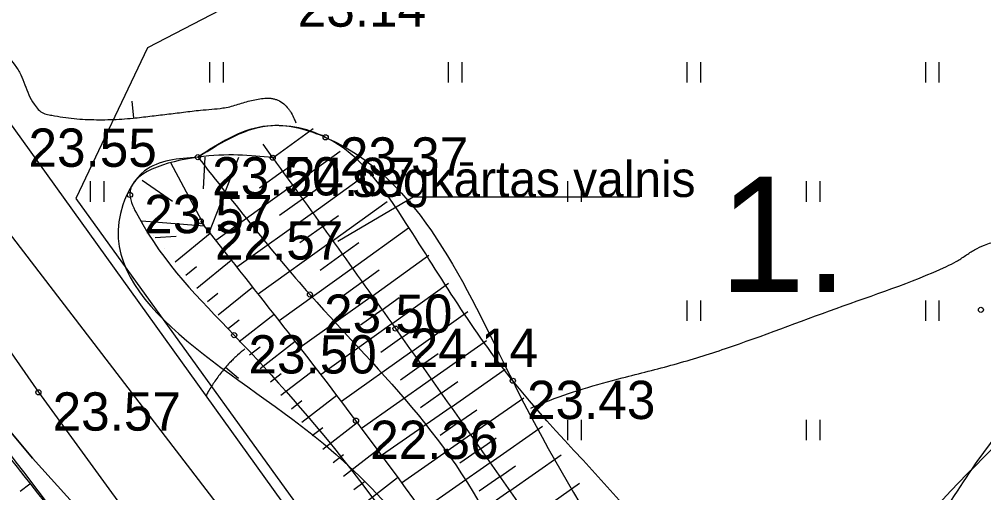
# Model space of a CAD drawing. Extents: x 521824 to 524158, y 294774 to 296228.
# Drawn here: x 522148.91 to 522177.2, y 295839.46 to 295853.36 of the extents above; entities that cross this region are included whole.
import ezdxf

# ---------------------------------------------------------------- set-up
doc = ezdxf.new("R2010")
doc.units = 0
for name, color, linetype in [('7315030100', 7, 'Continuous'), ('CELI_CMAL_####_####_#', 7, 'Continuous'), ('GL4 Segkartas izplatības laukums', 7, 'Continuous'), ('GL7 Citi Izplatības laukumi', 7, 'Continuous'), ('RELJ_AATZ_####_TKST_#', 7, 'Continuous'), ('RELJ_ELEM_####_####_#', 7, 'Continuous'), ('RELJ_HORZ_PAMT_####_#', 7, 'Continuous'), ('RELJ_NOGA_####_####_#', 7, 'Continuous'), ('RELJ_NOGL_####_####_#', 7, 'Continuous'), ('TERT_ELEM_####_####_#', 7, 'Continuous'), ('TERT_IZMT_####_TKST_#', 7, 'Continuous'), ('TERT_KONT_####_####_#', 7, 'Continuous')]:
    doc.layers.add(name, color=color, linetype=linetype)

msp = doc.modelspace()

# ---------------------------------------------------------------- linework, layer by layer
at = {"layer": '7315030100'}
msp.add_lwpolyline([(521982.6621484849, 296071.9435568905), (522030.78400000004, 296022.73900000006), (522033.5410000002, 296023.5089999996), (522041.3830000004, 296002.9110000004), (522075.3820000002, 295945.0490000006), (522118.8880000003, 295885.8499999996), (522163.66299999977, 295827.4399999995), (522159.46399999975, 295824.69800000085), (522114.8890000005, 295882.8479999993), (522071.2010000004, 295942.2949999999), (522036.86299999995, 296000.73299999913), (522028.99600000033, 296021.0460000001), (521979.24799999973, 296071.9199999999), (521979.2263936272, 296071.94480188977)], dxfattribs=at)
at = {"layer": 'CELI_CMAL_####_####_#'}
for points in [[(522172.092, 295817.657), (522166.319, 295825.15), (522160.036, 295834.4430000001), (522148.759, 295850.151), (522144.922, 295855.32800000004), (522137.14400000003, 295864.043), (522128.853, 295872.455), (522121.32200000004, 295880.759), (522112.36500000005, 295890.512), (522105.478, 295899.02900000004), (522098.35400000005, 295909.472), (522089.453644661, 295921.09464466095), (522081.842, 295931.152), (522074.717, 295941.169), (522065.954, 295953.62700000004)], [(522095.856, 295905.56700000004), (522095.856, 295905.56700000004), (522102.541, 295897.227), (522109.814, 295887.993), (522118.24600000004, 295878.42600000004), (522126.721, 295869.938), (522134.59400000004, 295861.6280000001), (522142.07200000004, 295853.04000000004), (522149.466, 295842.40400000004), (522156.738, 295832.411), (522163.775, 295823.088), (522169.38300000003, 295816.077)]]:
    msp.add_lwpolyline(points, dxfattribs=at)
at = {"layer": 'GL4 Segkartas izplatības laukums'}
msp.add_lwpolyline([(522247.30600000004, 295900.5950000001), (522229.308, 295886.109), (522196.01300000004, 295865.8560000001), (522191.022, 295861.577), (522188.2529917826, 295859.2030095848), (522185.84300000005, 295858.229), (522177.471, 295856.9160000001), (522169.67299667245, 295855.6930212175), (522168.16500000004, 295856.767), (522167.33, 295858.7370000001), (522158.998, 295858), (522156.91000000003, 295854.7370000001), (522152.672, 295852.521), (522150.56600000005, 295848.098), (522164.89497742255, 295828.2231119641), (522172.84800000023, 295833.39200000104), (522186.60753180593, 295842.8705587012), (522303.8134822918, 295923.6104775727)], dxfattribs=at)
msp.add_lwpolyline([(522247.30600000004, 295900.5950000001), (522229.308, 295886.109), (522196.01300000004, 295865.8560000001), (522191.022, 295861.577), (522188.2529917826, 295859.2030095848), (522185.84300000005, 295858.229), (522177.471, 295856.9160000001), (522169.67299667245, 295855.6930212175), (522168.16500000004, 295856.767), (522167.33, 295858.7370000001), (522158.998, 295858), (522156.91000000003, 295854.7370000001), (522152.672, 295852.521), (522150.56600000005, 295848.098), (522164.89497742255, 295828.2231119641), (522172.84800000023, 295833.39200000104), (522186.60753180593, 295842.8705587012), (522303.8134822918, 295923.6104775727)], dxfattribs=at)
msp.add_lwpolyline([(522069.63, 295797.668), (522066.6245064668, 295799.3774776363), (522066.821, 295800.191), (522078.81700000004, 295806.63300000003), (522081.268320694, 295807.8271870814), (522087.6908621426, 295812.09928898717), (522093.4905087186, 295816.2776405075), (522098.79571581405, 295820.26733720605), (522107.34300000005, 295832.723), (522111.787, 295855.21900000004), (522106.5222183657, 295875.48821839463), (522108.8492994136, 295877.62784059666), (522114.174, 295882.652), (522149.292, 295840.47000000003), (522151.58, 295837.93200000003), (522131.531, 295829.31200000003), (522119.09400000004, 295822.70800000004), (522104.069, 295811.941), (522092.118, 295802.865), (522086.39400000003, 295802.68), (522071.7450000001, 295796.673)], close=True, dxfattribs=at)
at = {"layer": 'GL7 Citi Izplatības laukumi'}
msp.add_lwpolyline([(522151.58, 295837.93200000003), (522149.292, 295840.47000000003), (522114.174, 295882.652), (522108.8492994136, 295877.62784059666), (522106.5222183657, 295875.48821839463), (522111.787, 295855.21900000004), (522107.34300000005, 295832.723), (522098.79571581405, 295820.26733720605), (522093.4905087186, 295816.2776405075), (522087.6908621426, 295812.09928898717), (522081.268320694, 295807.8271870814), (522078.81700000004, 295806.63300000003), (522066.821, 295800.191), (522066.6245064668, 295799.3774776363), (522069.63, 295797.668), (522071.7450000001, 295796.673), (522086.39400000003, 295802.68), (522092.118, 295802.865), (522104.069, 295811.941), (522119.09400000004, 295822.70800000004), (522131.531, 295829.31200000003)], dxfattribs=at)
at = {"layer": 'RELJ_ELEM_####_####_#'}
for centre in [(522157.895, 295849.892), (522154.14800000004, 295849.31), (522156.342, 295849.294), (522152.15400000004, 295848.202), (522154.23000000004, 295847.428), (522157.433, 295845.276), (522177.12200000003, 295844.826), (522155.212, 295844.082), (522159.944, 295844.276), (522163.386, 295842.744), (522149.466, 295842.40400000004), (522158.78500000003, 295841.572)]:
    msp.add_circle(centre, 0.075, dxfattribs=at)
at = {"layer": 'RELJ_HORZ_PAMT_####_#'}
for p, q in [((522152.20631230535, 295850.9548594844), (522152.25948074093, 295850.4576944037)), ((522155.3346348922, 295842.80943801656), (522154.95601187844, 295843.13600288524))]:
    msp.add_line(p, q, dxfattribs=at)
for points in [[(522163.9104526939, 295841.9398118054), (522163.9514715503, 295841.9570692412), (522164.32447347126, 295842.11259051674), (522166.59676086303, 295842.82732417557), (522168.11975066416, 295843.22458043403), (522169.62428788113, 295843.6895529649), (522172.8768601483, 295844.8696622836), (522176.1104548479, 295846.101839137), (522176.3950922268, 295846.24465798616), (522176.6657146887, 295846.4173670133), (522176.9365903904, 295846.5893884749), (522177.22198748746, 295846.7301446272), (522177.63320596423, 295846.8465723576), (522178.0586828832, 295846.91395572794), (522178.48716809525, 295846.9735594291), (522178.9074114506, 295847.06664815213), (522182.7973494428, 295848.4281834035), (522186.5482276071, 295850.1510005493), (522187.9526839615, 295851.1947113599), (522189.169375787, 295852.5039565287), (522190.40400233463, 295853.7852775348), (522191.0923221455, 295854.3237606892), (522191.8622628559, 295854.74521585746), (522192.759202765, 295854.9962647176), (522193.37150358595, 295855.0745775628), (522200.9836764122, 295855.41795290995), (522201.8852985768, 295855.4588233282), (522202.336347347, 295855.4581671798), (522202.7873160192, 295855.4210078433), (522203.4299293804, 295855.2599719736), (522204.09597616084, 295854.9702336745), (522204.7238502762, 295854.24504904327), (522204.2015930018, 295853.68376356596), (522203.40336924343, 295853.14374633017), (522202.2944243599, 295852.44411490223), (522200.65831003, 295851.5277301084), (522198.98511133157, 295850.6821143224), (522196.3444203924, 295849.60365764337), (522189.3202318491, 295847.27306183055), (522186.5369350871, 295846.40186535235), (522185.7070130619, 295846.16915820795), (522183.784125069, 295845.5400177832), (522181.9238943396, 295844.74614925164), (522180.18129871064, 295843.70893970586), (522179.37129463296, 295843.074515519), (522178.9846226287, 295842.7240494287), (522178.6113160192, 295842.34977623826), (522176.955044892, 295840.3029118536), (522175.60876787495, 295838.12981168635), (522174.4209128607, 295835.8876174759), (522173.2399077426, 295833.63347096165), (522173.06652449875, 295833.1648759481), (522172.82319235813, 295832.721657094), (522172.1500586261, 295832.4448160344), (522171.55004436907, 295832.31430290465), (522170.946402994, 295832.2057056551), (522170.3461095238, 295832.0875828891), (522170.140626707, 295832.04)], [(522146.576461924, 295853.0957484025), (522146.5764619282, 295853.09574840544), (522146.69775956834, 295853.16329074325), (522146.8262120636, 295853.20303598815), (522146.95633403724, 295853.21654107), (522147.08264011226, 295853.2053629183), (522147.38662802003, 295853.11871330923), (522147.6820829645, 295852.9713848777), (522148.27902005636, 295852.5280905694), (522148.77768095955, 295852.0097562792), (522148.95083036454, 295851.7316271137), (522149.06996416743, 295851.43776109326), (522149.18345684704, 295851.1448243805), (522149.33968288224, 295850.86948313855), (522149.61705139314, 295850.59789043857), (522149.69772556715, 295850.57328171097), (522149.77893267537, 295850.5544231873), (522149.94272394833, 295850.52504123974), (522150.26940348, 295850.47148762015), (522150.92529322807, 295850.41517027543), (522151.2549262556, 295850.40931911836), (522151.5849892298, 295850.4130686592), (522152.2437637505, 295850.45601726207), (522152.7392684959, 295850.51188784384), (522153.23403210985, 295850.57152802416), (522153.7285930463, 295850.63143016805), (522154.2234897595, 295850.68808664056), (522154.88001519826, 295850.75421472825), (522155.080483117, 295850.79110230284), (522155.2775007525, 295850.8471739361), (522155.47329517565, 295850.90882042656), (522155.670093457, 295850.9624325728), (522156.06048865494, 295851.0365902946), (522156.25787276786, 295851.0401016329), (522156.3552617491, 295851.02631688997), (522156.45107736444, 295850.99944862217), (522156.77056329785, 295850.77297377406), (522156.8330364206, 295850.69270858), (522156.88757810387, 295850.6098795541), (522156.9734581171, 295850.4335449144), (522157.0173121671, 295850.31808146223)], [(522155.52483055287, 295843.680422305), (522155.3115100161, 295843.49867381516), (522155.20935508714, 295843.402377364), (522155.10949660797, 295843.30303460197), (522154.86664333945, 295843.02860763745), (522154.75488565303, 295842.8836842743), (522154.64802492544, 295842.73447762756), (522154.45235664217, 295842.4248378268), (522154.38881749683, 295842.3090940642)]]:
    msp.add_spline(points, degree=3, dxfattribs=at)
at = {"layer": 'RELJ_NOGA_####_####_#'}
for p, q in [((522156.342, 295849.294), (522157.53171933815, 295850.1479994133)), ((522156.342, 295849.294), (522156.0574712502, 295849.69038125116)), ((522153.8432095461, 295849.28738562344), (522153.8432523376, 295849.28708869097)), ((522154.3483709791, 295849.30853877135), (522154.3025517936, 295848.3776813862)), ((522155.3420265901, 295849.3012924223), (522154.4785720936, 295847.10922683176)), ((522156.342, 295849.294), (522156.34118762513, 295849.2934168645)), ((522156.9251355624, 295848.4816251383), (522158.32282726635, 295849.48491041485)), ((522153.3413137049, 295849.1516506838), (522154.3274280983, 295847.3031205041)), ((522153.3609049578, 295849.1590950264), (522153.36126555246, 295849.15816230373)), ((522156.6335677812, 295848.88781256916), (522157.02994903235, 295849.172341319)), ((522152.9127268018, 295848.9390806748), (522152.91288240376, 295848.9388241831)), ((522156.6335677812, 295848.88781256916), (522155.9523318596, 295848.39881061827)), ((522157.5082711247, 295847.66925027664), (522159.02830212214, 295848.76035263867)), ((522152.51405981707, 295848.6386468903), (522153.40271442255, 295848.0162757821)), ((522156.9251355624, 295848.4816251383), (522154.67103885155, 295846.86359876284)), ((522157.2167033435, 295848.0754377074), (522157.65584527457, 295848.39066075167)), ((522157.2167033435, 295848.0754377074), (522156.5457413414, 295847.59381053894)), ((522158.0914066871, 295846.8568754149), (522159.6951633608, 295848.0080773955)), ((522152.23063880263, 295847.7984118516), (522152.23148378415, 295847.7989466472)), ((522157.5082711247, 295847.66925027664), (522155.2900036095, 295846.0769426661)), ((522157.7998389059, 295847.26306284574), (522158.2698159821, 295847.6004198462)), ((522152.50396417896, 295847.4387703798), (522154.3330034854, 295847.29571821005)), ((522152.53404650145, 295847.40130984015), (522152.53428078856, 295847.40149721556)), ((522157.7998389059, 295847.26306284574), (522157.1399555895, 295846.78938813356)), ((522152.84772989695, 295847.01194860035), (522152.8485076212, 295847.01257720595)), ((522152.8975685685, 295846.95033606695), (522153.5138854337, 295846.9873653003)), ((522153.47891221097, 295846.23631518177), (522154.50600436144, 295847.0742284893)), ((522158.6745422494, 295846.04450055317), (522160.32643880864, 295847.2302581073)), ((522158.0914066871, 295846.8568754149), (522155.9104761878, 295845.2913689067)), ((522158.38297446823, 295846.45068798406), (522158.87259029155, 295846.80214198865)), ((522153.1628686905, 295846.6237638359), (522153.16310155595, 295846.6239529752)), ((522158.38297446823, 295846.45068798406), (522157.73429948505, 295845.9850587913)), ((522159.2576778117, 295845.2321256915), (522160.9270028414, 295846.4303936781)), ((522154.110639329, 295845.461124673), (522155.1263628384, 295846.2844480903)), ((522153.7949082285, 295845.84882776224), (522154.1009233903, 295846.0982021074)), ((522158.6745422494, 295846.04450055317), (522156.530669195, 295844.5055944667)), ((522158.9661100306, 295845.6383131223), (522159.46534236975, 295845.9966700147)), ((522158.9661100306, 295845.6383131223), (522158.3282252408, 295845.1804293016)), ((522159.8408133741, 295844.4197508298), (522161.50248650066, 295845.61252615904)), ((522154.4252227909, 295845.07249011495), (522154.72926612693, 295845.31733587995)), ((522154.7381794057, 295844.68254458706), (522155.75330117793, 295845.4903544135)), ((522159.2576778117, 295845.2321256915), (522157.1482249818, 295843.71792698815)), ((522159.5492455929, 295844.82593826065), (522160.0497024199, 295845.18517410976)), ((522159.5492455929, 295844.82593826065), (522158.921096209, 295844.37504266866)), ((522160.4223576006, 295843.6062372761), (522162.06410219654, 295844.77530064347)), ((522155.0486245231, 295844.2905970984), (522155.35487034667, 295844.5304521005)), ((522155.35638259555, 295843.89653563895), (522156.38172753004, 295844.6947588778)), ((522159.8408133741, 295844.4197508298), (522157.7610135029, 295842.9268374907)), ((522160.13202473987, 295844.0133079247), (522160.6277706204, 295844.36814348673)), ((522155.97067449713, 295843.10745677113), (522156.99942898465, 295843.9083343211)), ((522160.13202473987, 295844.0133079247), (522159.51129611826, 295843.5690145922)), ((522161.0002018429, 295842.7900912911), (522162.61651856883, 295843.9288742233)), ((522155.66352854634, 295843.5019962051), (522155.971768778, 295843.7419588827)), ((522160.4223576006, 295843.6062372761), (522158.36140935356, 295842.1386648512)), ((522160.71173160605, 295843.1984842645), (522161.2004008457, 295843.5449767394)), ((522156.5842135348, 295842.31779241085), (522157.61398036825, 295843.1177998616)), ((522160.71173160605, 295843.1984842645), (522160.09570505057, 295842.76168868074)), ((522161.5752518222, 295841.97197333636), (522163.163711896, 295843.0842936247)), ((522156.27746362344, 295842.71263983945), (522156.5865544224, 295842.9527669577)), ((522161.0002018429, 295842.7900912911), (522158.9514406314, 295841.34662772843)), ((522161.28791648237, 295842.3811656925), (522161.7685596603, 295842.71871375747)), ((522157.1971252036, 295841.52764105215), (522158.2223604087, 295842.32264757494)), ((522161.28791648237, 295842.3811656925), (522160.6751796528, 295841.9508503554)), ((522162.14860231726, 295841.1526632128), (522163.7112847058, 295842.2452208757)), ((522156.89073121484, 295841.92276473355), (522157.19933388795, 295842.16206702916)), ((522161.5752518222, 295841.97197333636), (522159.5383342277, 295840.5456203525)), ((522161.86205190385, 295841.5624056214), (522162.3345153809, 295841.89324850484)), ((522157.50330097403, 295841.13234829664), (522157.8094800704, 295841.369376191)), ((522157.8093762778, 295840.7369777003), (522158.8224704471, 295841.5212623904)), ((522161.86205190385, 295841.5624056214), (522161.2530135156, 295841.13592606)), ((522162.7215999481, 295840.33310618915), (522164.2578939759, 295841.40721428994)), ((522162.14860231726, 295841.1526632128), (522160.1234795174, 295839.7367878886)), ((522162.4351011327, 295840.742884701), (522162.8999707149, 295841.0679007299)), ((522158.1151777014, 295840.34139523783), (522158.4165638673, 295840.5743662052)), ((522158.4208530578, 295839.94571537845), (522159.4158369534, 295840.71381948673)), ((522162.4351011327, 295840.742884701), (522161.82901428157, 295840.3191358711)), ((522163.29489909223, 295839.5137602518), (522164.80245411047, 295840.5705942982)), ((522162.7215999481, 295840.33310618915), (522160.70520035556, 295838.9233297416)), ((522163.0080987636, 295839.9233276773), (522163.46495080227, 295840.2427381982)), ((522159.0315514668, 295839.1538522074), (522160.003737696, 295839.90305976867)), ((522163.0080987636, 295839.9233276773), (522162.40407044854, 295839.5010180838)), ((522149.21182324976, 295839.7109763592), (522148.9318465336, 295839.4923274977)), ((522158.7263450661, 295839.5498939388), (522159.0216350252, 295839.77745679)), ((522163.870052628, 295838.69571539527), (522165.3447788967, 295839.73524792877)), ((522163.29489909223, 295839.5137602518), (522161.2850579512, 295838.10481097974))]:
    msp.add_line(p, q, dxfattribs=at)
for points in [[(522157.9073553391, 295825.4033553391), (522159.06600000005, 295826.51800000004), (522156.80645671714, 295830.2750716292), (522151.05064466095, 295837.373355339), (522142.526, 295848.184), (522133.612, 295858.662), (522124.39, 295869.90400000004), (522117.34943299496, 295878.46614491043), (522115.10500000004, 295880.075), (522113.824, 295878.38800000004)], [(522156.272, 295825.614), (522148.59400000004, 295834.485), (522139.96300000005, 295845.118), (522131.29600000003, 295855.769), (522123.482, 295864.8780000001), (522113.51, 295876.949)], [(522156.342, 295849.294), (522154.14800000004, 295849.31), (522152.15400000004, 295848.202), (522152.3815789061, 295847.59194952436), (522155.212, 295844.082), (522161.494, 295835.946), (522165.36600000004, 295829.941), (522166.14176769, 295829.3592155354), (522168.058, 295830.359)], [(522156.342, 295849.294), (522159.944, 295844.276), (522164.348, 295838.02), (522166.93213962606, 295834.51182570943), (522167.837, 295833.179), (522168.058, 295830.359)]]:
    msp.add_spline(points, degree=3, dxfattribs=at)
at = {"layer": 'RELJ_NOGL_####_####_#'}
for points in [[(522157.77300000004, 295827.023), (522157.87200000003, 295825.368), (522156.8138430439, 295824.483601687), (522155.071, 295825.376), (522154.4157255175, 295826.43018908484), (522151.8136290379, 295829.3257378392), (522140.98600000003, 295841.081), (522130.14800000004, 295854.6060000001), (522118.868, 295867.895), (522112.737, 295876.058), (522113.2986392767, 295878.0255479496), (522113.824, 295878.38800000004), (522115.39200000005, 295878.049)], [(522157.77300000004, 295827.023), (522147.977, 295839.362), (522140.016, 295849.58900000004), (522131.454, 295859.47500000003), (522123.498, 295869.164), (522115.39200000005, 295878.049)], [(522154.14800000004, 295849.31), (522156.33940066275, 295850.24236979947), (522157.895, 295849.892), (522163.36304643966, 295842.77831977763), (522169.94800000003, 295832.54000000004), (522170.20455015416, 295832.0913783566), (522169.51738907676, 295831.2218695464), (522168.058, 295830.359)], [(522166.32, 295830.885), (522158.78500000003, 295841.572), (522154.23000000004, 295847.428)]]:
    msp.add_spline(points, degree=3, dxfattribs=at)
at = {"layer": 'TERT_ELEM_####_####_#'}
for p, q in [((522154.5, 295851.5), (522154.5, 295852.10000000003)), ((522154.9, 295851.5), (522154.9, 295852.10000000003)), ((522161.5, 295851.5), (522161.5, 295852.10000000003)), ((522161.9, 295851.5), (522161.9, 295852.10000000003)), ((522168.5, 295851.5), (522168.5, 295852.10000000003)), ((522168.9, 295851.5), (522168.9, 295852.10000000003)), ((522175.5, 295851.5), (522175.5, 295852.10000000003)), ((522175.9, 295851.5), (522175.9, 295852.10000000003)), ((522151, 295848), (522151, 295848.60000000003)), ((522151.4, 295848), (522151.4, 295848.60000000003)), ((522165, 295848), (522165, 295848.60000000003)), ((522165.4, 295848), (522165.4, 295848.60000000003)), ((522172, 295848), (522172, 295848.60000000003)), ((522172.4, 295848), (522172.4, 295848.60000000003)), ((522168.5, 295844.5), (522168.5, 295845.10000000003)), ((522168.9, 295844.5), (522168.9, 295845.10000000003)), ((522175.5, 295844.5), (522175.5, 295845.10000000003)), ((522175.9, 295844.5), (522175.9, 295845.10000000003)), ((522165, 295841), (522165, 295841.60000000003)), ((522165.4, 295841), (522165.4, 295841.60000000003)), ((522172, 295841), (522172, 295841.60000000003)), ((522172.4, 295841), (522172.4, 295841.60000000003))]:
    msp.add_line(p, q, dxfattribs=at)
at = {"layer": 'TERT_IZMT_####_TKST_#'}
msp.add_lwpolyline([(522167.1093085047, 295848.13882695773), (522160.4613142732, 295848.13882695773), (522158.25645186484, 295846.835213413)], dxfattribs=at)
at = {"layer": 'TERT_KONT_####_####_#'}
for points in [[(522112.737, 295876.058), (522112.737, 295877.51455323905), (522113.8446896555, 295878.3905175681), (522123.086, 295867.722), (522132.03, 295856.813), (522140.951, 295846.381), (522148.93700000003, 295836.168), (522157.87200000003, 295825.368), (522156.95989990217, 295824.47003253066), (522155.7794142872, 295824.7184870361), (522155.071, 295825.376), (522140.98600000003, 295841.081), (522129.85114007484, 295854.43447290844), (522118.868, 295867.895), (522112.737, 295876.058)], [(522113.824, 295878.38800000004), (522115.10500000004, 295880.075), (522116.5519780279, 295879.5176271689), (522128.1031053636, 295865.4696861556), (522131.4996345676, 295861.338800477), (522136.521227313, 295855.31825432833), (522141.58674069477, 295849.3855993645), (522147.8381112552, 295841.49004127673), (522154.279804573, 295833.447997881), (522158.86219095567, 295828.02804149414), (522159.4038788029, 295827.0319414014), (522158.9939528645, 295826.19697514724), (522157.9115556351, 295825.277834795)], [(522210.195, 295852.81900000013), (522208.8355751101, 295853.6174840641), (522196.72900000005, 295849.161), (522185.79600000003, 295846.375), (522169.94800000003, 295832.54000000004), (522168.0970000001, 295830.30399999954), (522179.2164650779, 295816.83799667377)], [(522168.15669273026, 295830.23751669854), (522181.77900000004, 295837.08300000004), (522199.31, 295846.865), (522210.195, 295852.81900000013)], [(522154.14800000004, 295849.31), (522156.05225736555, 295850.2081574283), (522157.895, 295849.892), (522160.26119203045, 295847.36355651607), (522163.386, 295842.744), (522169.94800000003, 295832.54000000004), (522169.72786443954, 295831.17398676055), (522168.058, 295830.359), (522163.292, 295837.349), (522157.433, 295845.276), (522154.14800000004, 295849.31)], [(522154.14800000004, 295849.31), (522152.5811908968, 295848.9037850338), (522151.94435984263, 295847.9081711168), (522157.437027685, 295841.2176455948), (522165.56393418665, 295829.6579584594), (522165.9546430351, 295829.1508049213), (522168.058, 295830.359)]]:
    msp.add_spline(points, degree=3, dxfattribs=at)

# ---------------------------------------------------------------- texts
at = {"layer": 'GL4 Segkartas izplatības laukums'}
msp.add_text('1.', height=3.3819853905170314, dxfattribs=at).set_placement((522169.4484622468, 295845.3521994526))
at = {"layer": 'RELJ_AATZ_####_TKST_#'}
for s, p in [(' 23.14', (522156.66000000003, 295853.141)), (' 23.55', (522148.759, 295849.026)), (' 23.37', (522157.895, 295848.767)), (' 23.50', (522154.14800000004, 295848.185)), (' 24.07', (522156.342, 295848.169)), (' 23.57', (522152.15400000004, 295847.077)), (' 22.57', (522154.23000000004, 295846.303)), (' 23.50', (522157.433, 295844.151)), (' 24.14', (522159.944, 295843.151)), (' 23.50', (522155.212, 295842.957)), (' 23.43', (522163.386, 295841.619)), (' 23.57', (522149.466, 295841.27900000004)), (' 22.36', (522158.78500000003, 295840.447))]:
    msp.add_text(s, height=1.125, dxfattribs=at).set_placement(p)
at = {"layer": 'TERT_IZMT_####_TKST_#'}
msp.add_text('segkārtas valnis', height=1.0499999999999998, dxfattribs=at).set_placement((522158.6810237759, 295848.14028627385))

doc.saveas('drawing.dxf')
